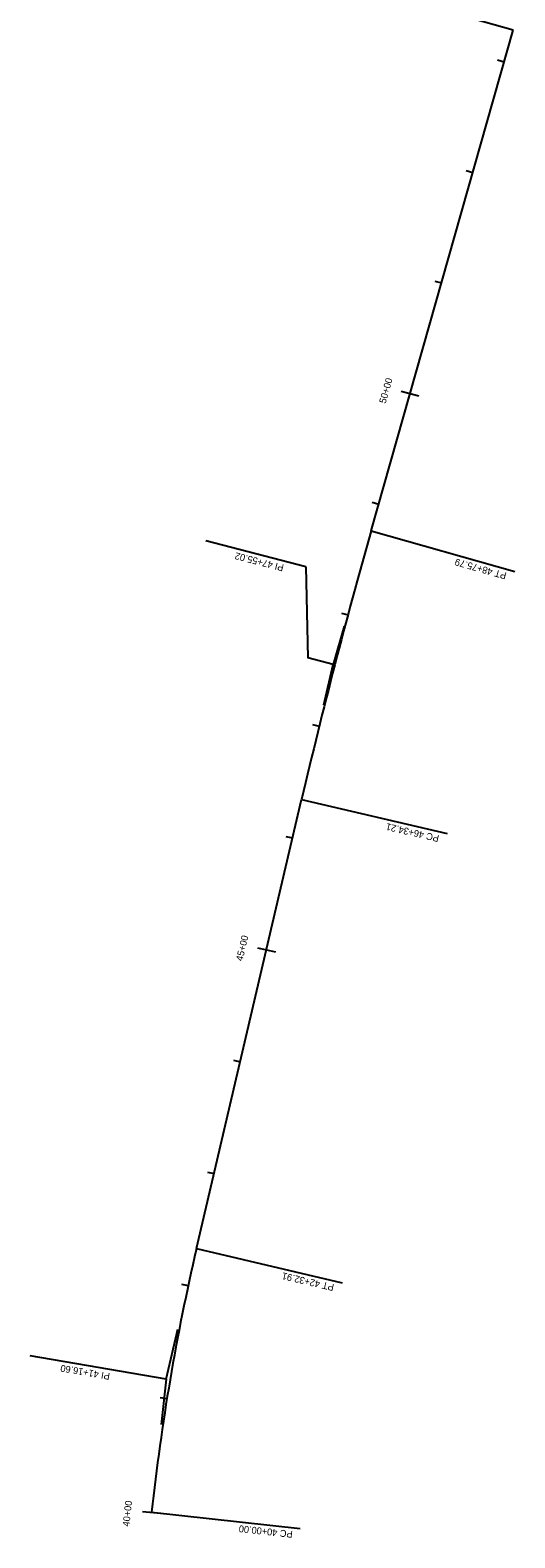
# Model space of a CAD drawing. Extents: x 1445613 to 1446340, y 2043492 to 2056486.
# Drawn here: x 1445613 to 1446035, y 2053844 to 2055156 of the extents above; entities that cross this region are included whole.
import ezdxf

# ---------------------------------------------------------------- set-up
doc = ezdxf.new("R2010")
doc.units = 0
for name, color, linetype in [('R_Horz Alg', 7, 'Continuous'), ('R_Horz Alg Annot_Detour', 7, 'Continuous'), ('R_Horz Alg Stationing_Detour', 7, 'Continuous')]:
    doc.layers.add(name, color=color, linetype=linetype)

msp = doc.modelspace()

# ---------------------------------------------------------------- linework, layer by layer
at = {"layer": 'R_Horz Alg'}
for p, q in [((1445909.6, 2054720), (1446033.2, 2055155.6)), ((1445757.7, 2054095.3), (1445849.1, 2054486.1))]:
    msp.add_line(p, q, dxfattribs=at)
for centre, radius, start, end in [((1450897.1, 2053305.5), 5184.2, 164.1667, 166.8366), ((1447617.4, 2053660.4), 1909.9, 166.8366, 173.8239)]:
    msp.add_arc(centre, radius, start, end, dxfattribs=at)
at = {"layer": 'R_Horz Alg Annot_Detour'}
for p, q in [((1445852.8, 2054688.7), (1445854.5, 2054609.4)), ((1445886.1, 2054636.9), (1445876.6, 2054603.7)), ((1445868.4, 2054568.6), (1445876.6, 2054603.7)), ((1445731.2, 2053981.8), (1445741.4, 2054025.3)), ((1445731.2, 2053981.8), (1445726.9, 2053942.2))]:
    msp.add_line(p, q, dxfattribs=at)
for points in [[(1446033.2, 2055155.6), (1445908.1, 2055191.1)], [(1445909.6, 2054720), (1446034.7, 2054684.5)], [(1445852.8, 2054688.7), (1445765.8, 2054711.2)], [(1445876.6, 2054603.7), (1445854.5, 2054609.4)], [(1445849.1, 2054486.1), (1445975.7, 2054456.5)], [(1445757.7, 2054095.3), (1445884.3, 2054065.7)], [(1445731.2, 2053981.8), (1445612.9, 2054002)], [(1445718.6, 2053865.9), (1445847.9, 2053851.9)]]:
    msp.add_lwpolyline(points, dxfattribs=at)
at = {"layer": 'R_Horz Alg Stationing_Detour'}
for points in [[(1446019.6, 2055129.7), (1446025.3, 2055128.1)], [(1445992.3, 2055033.5), (1445998.1, 2055031.9)], [(1445965, 2054937.3), (1445970.8, 2054935.7)], [(1445935.8, 2054841.6), (1445951.2, 2054837.3)], [(1445910.4, 2054744.9), (1445916.2, 2054743.2)], [(1445883.7, 2054648.4), (1445889.5, 2054646.9)], [(1445858.7, 2054551.5), (1445864.5, 2054550.1)], [(1445835.5, 2054454.1), (1445841.3, 2054452.8)], [(1445810.8, 2054357.2), (1445826.3, 2054353.6)], [(1445789.9, 2054259.4), (1445795.8, 2054258)], [(1445767.2, 2054162), (1445773, 2054160.7)], [(1445744.7, 2054064.5), (1445750.5, 2054063.2)], [(1445726.1, 2053965.9), (1445732, 2053965)], [(1445710.7, 2053866.7), (1445726.6, 2053865)]]:
    msp.add_lwpolyline(points, dxfattribs=at)

# ---------------------------------------------------------------- texts
at = {"layer": 'R_Horz Alg Annot_Detour'}
for s, rotation, p in [('PI 47+55.02', 165.5016, (1445834.1, 2054690.4)), ('PT 48+75.79', 164.1667, (1446027.9, 2054683.4)), ('PC 46+34.21', 166.8366, (1445969.2, 2054454.9)), ('PT 42+32.91', 166.8366, (1445877.8, 2054064.2)), ('PI 41+16.60', 170.3303, (1445682.7, 2053987)), ('PC 40+00.00', 173.8239, (1445841.6, 2053849.6))]:
    msp.add_text(s, height=6, rotation=rotation, dxfattribs=at).set_placement(p)
at = {"layer": 'R_Horz Alg Stationing_Detour'}
for s, rotation, p in [('50+00', 74.1667, (1445922.2, 2054830.3)), ('45+00', 76.8366, (1445797.7, 2054345.2)), ('40+00', 83.8239, (1445699.2, 2053853.3))]:
    msp.add_text(s, height=6, rotation=rotation, dxfattribs=at).set_placement(p)

doc.saveas('drawing.dxf')
